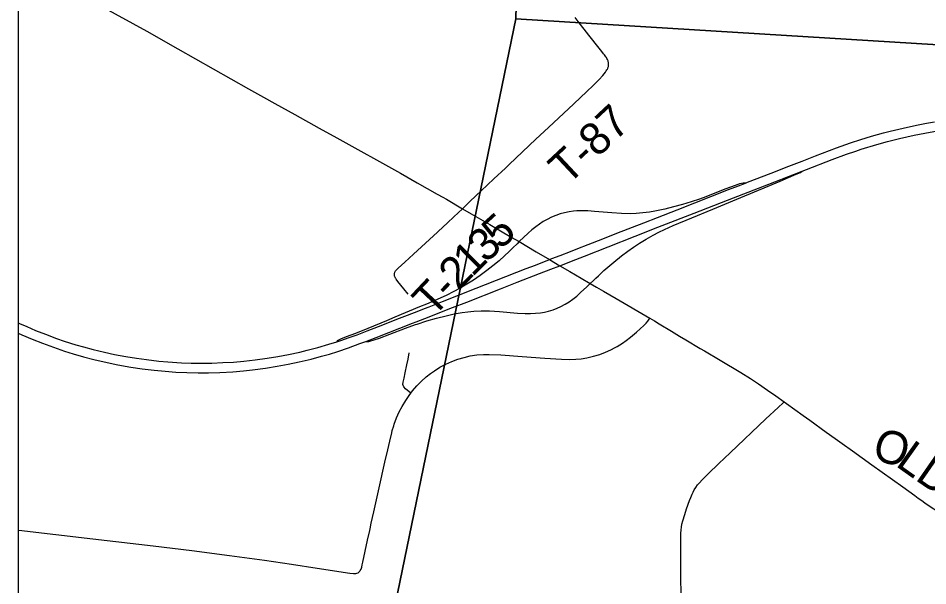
# Model space of a CAD drawing. Extents: x -13.9 to 69.1, y -25.2 to 26.1.
# Drawn here: x 1.757 to 3.245, y 17.974 to 18.903 of the extents above; entities that cross this region are included whole.
import ezdxf

# ---------------------------------------------------------------- set-up
doc = ezdxf.new("R2010")
doc.units = 0
for name, color, linetype in [('GM_X_County_Road', 7, 'Continuous'), ('GM_X_County_Road_Text', 7, 'Continuous'), ('GM_X_Interchange_Ramps', 7, 'Continuous'), ('GM_X_Township', 7, 'Continuous'), ('GM_X_Township_Road', 7, 'Continuous'), ('GM_X_Township_Road_Text', 7, 'Continuous'), ('GM_X_US_Route', 7, 'Continuous'), ('SH_Data', 7, 'Continuous')]:
    doc.layers.add(name, color=color, linetype=linetype)

msp = doc.modelspace()

# ---------------------------------------------------------------- linework, layer by layer
at = {"layer": 'GM_X_County_Road'}
for points in [[(1.8658, 18.9379), (1.8927, 18.9232), (1.9675, 18.8821), (2.0184, 18.8534), (2.1339, 18.788), (2.1583, 18.7741), (2.177, 18.7638), (2.2094, 18.7457), (2.2492, 18.7235), (2.2782, 18.7076), (2.3823, 18.6498), (2.4096, 18.6341), (2.4426, 18.6155)], [(2.4426, 18.6155), (2.4517, 18.6103), (2.4575, 18.607)], [(2.4575, 18.607), (2.4841, 18.5917)], [(2.4841, 18.5917), (2.4981, 18.5835), (2.5287, 18.5656), (2.5634, 18.5453), (2.5768, 18.5377)], [(2.5768, 18.5377), (2.6046, 18.5211), (2.6263, 18.5084), (2.6433, 18.4984), (2.6593, 18.489), (2.6782, 18.4779), (2.6928, 18.4694)], [(2.6928, 18.4694), (2.7033, 18.4633), (2.7147, 18.4566), (2.7352, 18.4447), (2.7906, 18.4124)], [(2.7906, 18.4124), (2.7979, 18.408), (2.8055, 18.4035), (2.8256, 18.3913), (2.8391, 18.3832), (2.8492, 18.3771), (2.8729, 18.3629)], [(2.8729, 18.3629), (2.8796, 18.3589), (2.9052, 18.3436), (2.9391, 18.3235), (2.9549, 18.3138), (2.9682, 18.3051), (2.9831, 18.2949), (2.9965, 18.2854), (3.0099, 18.2757)], [(2.8417, 17.9518), (2.8412, 17.9976), (2.8409, 18.047), (2.8413, 18.06), (2.8414, 18.066), (2.842, 18.0705), (2.8429, 18.0753), (2.8444, 18.0809), (2.8474, 18.0911), (2.8505, 18.1006), (2.8553, 18.1139), (2.8572, 18.119), (2.8596, 18.1244), (2.8612, 18.1278), (2.8631, 18.1314), (2.8656, 18.1353), (2.8686, 18.1396), (2.8714, 18.1432), (2.8758, 18.1477), (2.8856, 18.158), (2.903, 18.1744), (2.9218, 18.1921), (2.9803, 18.2475), (3.0002, 18.2664), (3.0083, 18.2742), (3.0099, 18.2757)], [(3.0099, 18.2757), (3.0139, 18.2728), (3.041, 18.2533), (3.0521, 18.2455), (3.0787, 18.2262), (3.0935, 18.2158), (3.1049, 18.2075), (3.1218, 18.1954), (3.1535, 18.1725), (3.2042, 18.1363), (3.2238, 18.1223), (3.2292, 18.1182), (3.2352, 18.114), (3.2403, 18.1104), (3.2524, 18.1022), (3.2595, 18.0976), (3.272, 18.09), (3.288, 18.0806), (3.3176, 18.0633), (3.3308, 18.0556)]]:
    msp.add_lwpolyline(points, dxfattribs=at)
at = {"layer": 'GM_X_Interchange_Ramps'}
for points in [[(2.6928, 18.4694), (2.6981, 18.4742), (2.7018, 18.4777), (2.7062, 18.4818), (2.7152, 18.4903), (2.7217, 18.4962), (2.7313, 18.5042), (2.7442, 18.5144), (2.7542, 18.522), (2.7639, 18.5288), (2.7733, 18.5351), (2.7843, 18.5419), (2.7956, 18.5483), (2.805, 18.5532), (2.8146, 18.5578), (2.8284, 18.564), (2.8589, 18.5765), (2.8935, 18.5908), (2.9394, 18.61), (2.984, 18.6287), (3.0034, 18.6369), (3.0258, 18.6463), (3.0353, 18.6502), (3.0367, 18.651), (3.0396, 18.6533)], [(2.9471, 18.6336), (2.9428, 18.6332), (2.9404, 18.633), (2.9373, 18.6323), (2.9341, 18.6312), (2.9299, 18.6297), (2.9147, 18.6242), (2.8995, 18.6183), (2.882, 18.6113), (2.8715, 18.6074), (2.8578, 18.6028), (2.844, 18.5987), (2.8289, 18.5946), (2.8147, 18.5909), (2.8066, 18.589), (2.7986, 18.5875), (2.7897, 18.586), (2.779, 18.5847), (2.7679, 18.5838), (2.759, 18.5834), (2.7441, 18.5839), (2.7281, 18.5849), (2.7, 18.5872), (2.6889, 18.5879), (2.6801, 18.5882), (2.6712, 18.588), (2.6657, 18.5876), (2.6586, 18.5867), (2.6505, 18.585), (2.6435, 18.583), (2.6367, 18.5806), (2.6295, 18.5776), (2.6224, 18.5741), (2.6161, 18.5705), (2.6099, 18.5665), (2.604, 18.5622), (2.5974, 18.5568), (2.5915, 18.5514), (2.5768, 18.5377)], [(2.5768, 18.5377), (2.5731, 18.5342), (2.566, 18.5276), (2.5601, 18.5214), (2.5527, 18.5143), (2.5438, 18.5063), (2.5337, 18.498), (2.5239, 18.4903), (2.5129, 18.4823), (2.5017, 18.4747), (2.4912, 18.4681), (2.48, 18.4616), (2.4686, 18.4555), (2.4581, 18.4503), (2.4424, 18.443), (2.4249, 18.4356), (2.4137, 18.4309), (2.3734, 18.4142), (2.3594, 18.4084), (2.329, 18.3957), (2.3088, 18.3875), (2.2937, 18.3817), (2.2845, 18.3783), (2.282, 18.3771), (2.2801, 18.3761), (2.279, 18.3752), (2.2782, 18.3739)], [(2.3259, 18.3745), (2.3286, 18.3741), (2.3305, 18.3743), (2.3324, 18.3747), (2.3483, 18.38), (2.365, 18.3862), (2.3906, 18.3959), (2.4073, 18.4019), (2.41, 18.4029), (2.4253, 18.4079), (2.4414, 18.4125), (2.457, 18.4164), (2.4705, 18.4194), (2.4831, 18.4216), (2.4924, 18.4229), (2.5023, 18.4239), (2.5145, 18.4245), (2.5283, 18.4244), (2.5443, 18.4234), (2.5741, 18.4209), (2.5863, 18.4202), (2.5951, 18.4202), (2.6034, 18.4205), (2.6117, 18.4214), (2.6182, 18.4225), (2.6247, 18.424), (2.6322, 18.4262), (2.6389, 18.4288), (2.645, 18.4316), (2.6519, 18.4354), (2.6582, 18.4392), (2.6642, 18.4434), (2.6709, 18.4487), (2.6772, 18.4545), (2.6872, 18.4639), (2.6928, 18.4694)]]:
    msp.add_lwpolyline(points, dxfattribs=at)
at = {"layer": 'GM_X_Township'}
msp.add_lwpolyline([(8.0976, 21.2145), (2.668, 21.2145), (2.5713, 21.1249), (2.5376, 21.0933), (2.5207, 21.0774), (2.9282, 20.5283), (2.3149, 19.9943), (2.3345, 19.9924), (2.4186, 19.989), (2.4692, 19.987), (2.5176, 19.987), (2.5995, 20.0118), (2.5714, 18.9023), (4.5288, 18.7816), (7.8661, 18.459), (7.9988, 20.0382), (8.0428, 20.5625)], close=True, dxfattribs=at)
for points in [[(2.2023, 16.145), (2.216, 16.457), (2.1711, 16.462), (2.1794, 16.5325), (2.2304, 17.2467), (2.5714, 18.9023), (2.5995, 20.0118)], [(1.7571, 19.5083), (1.7571, 15.7823)], [(7.8661, 18.459), (4.5288, 18.7816), (2.5714, 18.9023), (2.2304, 17.2467), (2.1794, 16.5325), (2.1711, 16.462), (2.216, 16.457), (2.2023, 16.145)]]:
    msp.add_lwpolyline(points, dxfattribs=at)
at = {"layer": 'GM_X_Township_Road'}
for points in [[(2.5542, 18.6582), (2.5604, 18.6639), (2.604, 18.7052), (2.6244, 18.7244), (2.6662, 18.7633), (2.6875, 18.7832), (2.6978, 18.7932), (2.7073, 18.8031), (2.7136, 18.8099), (2.718, 18.8153), (2.7192, 18.8172), (2.7201, 18.8188), (2.7209, 18.8201), (2.7214, 18.8213), (2.7218, 18.8222), (2.7222, 18.8234), (2.7225, 18.8245), (2.7227, 18.826), (2.7228, 18.8271), (2.7228, 18.8283), (2.7227, 18.8295), (2.7226, 18.8309), (2.7224, 18.8322), (2.7221, 18.8334), (2.7217, 18.8344), (2.7212, 18.8356), (2.7202, 18.8376), (2.7193, 18.839), (2.7185, 18.8403), (2.7174, 18.8417), (2.7161, 18.8435), (2.7147, 18.8452), (2.7118, 18.8488), (2.7074, 18.8542), (2.6905, 18.8755), (2.6733, 18.898), (2.6683, 18.9045)], [(2.4841, 18.5917), (2.4898, 18.5972), (2.4967, 18.604), (2.5146, 18.6209), (2.5354, 18.6405), (2.5542, 18.6582)], [(2.4429, 18.5533), (2.4442, 18.5545), (2.4593, 18.5684), (2.4697, 18.5782), (2.4841, 18.5917)], [(2.3949, 18.4518), (2.3879, 18.4603), (2.3781, 18.4725), (2.3754, 18.4763), (2.3748, 18.4773), (2.3743, 18.4781), (2.3736, 18.4795), (2.3732, 18.4804), (2.3729, 18.4814), (2.3728, 18.4822), (2.3727, 18.4833), (2.3726, 18.4843), (2.3727, 18.4852), (2.3729, 18.4863), (2.3731, 18.4872), (2.3734, 18.488), (2.3739, 18.4889), (2.3743, 18.4897), (2.3751, 18.4906), (2.3758, 18.4915), (2.3769, 18.4927), (2.3786, 18.4943), (2.3896, 18.5043), (2.4039, 18.5173), (2.4429, 18.5533)], [(2.7335, 18.3643), (2.7367, 18.366), (2.7457, 18.3716), (2.7517, 18.3758), (2.7588, 18.3813), (2.7688, 18.3898), (2.7806, 18.4006), (2.7842, 18.4042), (2.7871, 18.4076), (2.7906, 18.4124)], [(2.3993, 18.2899), (2.4021, 18.2936), (2.409, 18.3015), (2.4166, 18.3093), (2.4247, 18.3166), (2.4314, 18.3219), (2.4379, 18.3265), (2.4471, 18.3322), (2.4565, 18.3373), (2.4662, 18.3418), (2.4762, 18.3454), (2.4864, 18.3484), (2.4962, 18.3506), (2.5072, 18.3523), (2.5183, 18.3531), (2.5277, 18.353), (2.5465, 18.3524), (2.5813, 18.35), (2.6188, 18.3471), (2.6458, 18.3454), (2.6596, 18.3451), (2.6695, 18.3454), (2.6783, 18.3462), (2.6875, 18.3477), (2.6983, 18.3501), (2.7088, 18.3533), (2.7177, 18.3566), (2.7263, 18.3605), (2.7335, 18.3643)], [(2.3865, 18.3039), (2.3869, 18.3076), (2.3879, 18.3122), (2.3883, 18.3141), (2.3903, 18.3233), (2.3931, 18.3362), (2.395, 18.3453), (2.3969, 18.3557)], [(2.3993, 18.2899), (2.3908, 18.2968), (2.388, 18.3003), (2.3865, 18.3039)], [(2.3714, 18.2361), (2.3724, 18.2393), (2.3761, 18.2493), (2.3804, 18.259), (2.385, 18.2679), (2.391, 18.278), (2.3965, 18.2862), (2.3993, 18.2899)], [(2.3683, 18.2251), (2.3691, 18.2285), (2.3714, 18.2361)], [(2.3616, 18.1973), (2.3648, 18.2112), (2.3683, 18.2251)], [(2.3347, 18.0771), (2.3386, 18.0956), (2.3476, 18.1349), (2.3571, 18.1771), (2.3616, 18.1973)], [(1.7571, 18.0654), (1.7581, 18.0653), (1.879, 18.0512), (1.978, 18.0397), (2.0412, 18.0322), (2.1026, 18.0243), (2.1602, 18.0165), (2.2041, 18.0101), (2.2462, 18.0036), (2.2998, 17.9953), (2.3058, 17.9947), (2.3095, 17.9949), (2.3112, 17.9953), (2.313, 17.996), (2.3143, 17.9971), (2.3157, 17.9983), (2.3166, 17.9994)], [(2.3166, 17.9994), (2.318, 18.002), (2.3191, 18.0051), (2.32, 18.0086), (2.3211, 18.0133), (2.3286, 18.0493), (2.3321, 18.065)], [(2.3321, 18.065), (2.3327, 18.0678), (2.3347, 18.0771)]]:
    msp.add_lwpolyline(points, dxfattribs=at)
at = {"layer": 'GM_X_US_Route'}
for points in [[(1.7571, 18.4048), (1.7592, 18.4038), (1.771, 18.3986), (1.7855, 18.3925), (1.8016, 18.3862), (1.8199, 18.3795), (1.8325, 18.3751), (1.8516, 18.369), (1.8639, 18.3655), (1.8795, 18.3613), (1.8984, 18.3569), (1.9147, 18.3533), (1.9332, 18.3498), (1.9507, 18.3469), (1.9672, 18.3446), (1.987, 18.3423), (2.0019, 18.3409), (2.0245, 18.3395), (2.04, 18.339), (2.0561, 18.3388), (2.0738, 18.339), (2.092, 18.3397), (2.1092, 18.3407), (2.1263, 18.3422), (2.145, 18.3442), (2.1642, 18.3469), (2.1817, 18.3498), (2.1991, 18.353), (2.2176, 18.357), (2.23, 18.36), (2.2472, 18.3646), (2.2654, 18.3698), (2.2782, 18.3739), (2.285, 18.376), (2.2987, 18.3807), (2.3118, 18.3854), (2.328, 18.3916), (2.3467, 18.399), (2.381, 18.4124), (2.394, 18.4174), (2.4123, 18.4246), (2.4215, 18.4282), (2.4293, 18.4313), (2.4511, 18.4399), (2.5062, 18.4614), (2.5882, 18.4936), (2.6033, 18.4994), (2.6263, 18.5084), (2.6303, 18.51), (2.6439, 18.5152), (2.6605, 18.5216), (2.6724, 18.5264), (2.6896, 18.533), (2.7135, 18.5422), (2.7363, 18.5514), (2.7805, 18.5687), (2.8028, 18.5773), (2.8351, 18.5898), (2.9192, 18.6228), (2.9354, 18.629), (2.9471, 18.6336), (2.9504, 18.6349), (2.9889, 18.6498), (3.018, 18.6612), (3.0393, 18.6697), (3.0616, 18.6784), (3.0955, 18.6912), (3.1186, 18.6994), (3.1355, 18.7049), (3.153, 18.7102), (3.1728, 18.7157), (3.1836, 18.7184), (3.2046, 18.7234), (3.2268, 18.7282), (3.2431, 18.7314), (3.2562, 18.7337)], [(2.6584, 18.5043), (2.6623, 18.5058), (2.6836, 18.5141), (2.722, 18.5292), (2.7661, 18.5467), (2.8035, 18.5612), (2.8249, 18.5695), (2.8488, 18.5788), (2.8628, 18.5843), (2.9173, 18.6057), (2.9948, 18.6358), (3.0396, 18.6533), (3.0467, 18.656), (3.0889, 18.6722), (3.1119, 18.6807), (3.1272, 18.686), (3.1362, 18.689), (3.1618, 18.6968), (3.1794, 18.7017), (3.1988, 18.7066), (3.2227, 18.7119), (3.2401, 18.7155), (3.2608, 18.7192)], [(1.7571, 18.3877), (1.7632, 18.385), (1.7797, 18.3781), (1.7968, 18.3714), (1.8146, 18.3649), (1.833, 18.3586), (1.8473, 18.3541), (1.8638, 18.3493), (1.881, 18.3447), (1.9026, 18.3397), (1.9199, 18.3361), (1.9412, 18.3324), (1.9598, 18.3297), (1.9795, 18.3273), (1.9977, 18.3256), (2.0148, 18.3243), (2.033, 18.3234), (2.0517, 18.323), (2.0683, 18.3231), (2.0871, 18.3237), (2.108, 18.3248), (2.1256, 18.3263), (2.1405, 18.3279), (2.1619, 18.3308), (2.181, 18.3338), (2.1989, 18.3371), (2.2168, 18.3409), (2.2362, 18.3455), (2.2534, 18.3501), (2.2662, 18.3538), (2.2799, 18.3582), (2.2973, 18.364), (2.3162, 18.3708), (2.3259, 18.3745), (2.3428, 18.3809), (2.4019, 18.4042), (2.4083, 18.4067), (2.4222, 18.4122), (2.4674, 18.4297), (2.4908, 18.4389), (2.5459, 18.4605), (2.5734, 18.4713), (2.6098, 18.4854), (2.6285, 18.4927), (2.6433, 18.4984), (2.6584, 18.5043)]]:
    msp.add_lwpolyline(points, dxfattribs=at)
at = {"layer": 'SH_Data'}
msp.add_line((1.7571, 21.2145), (1.7571, 14.4145), dxfattribs=at)

# ---------------------------------------------------------------- texts
at = {"layer": 'GM_X_County_Road_Text'}
for s, height, rotation, p in [('O', 0.0541, 342.755, (3.1516, 18.1832)), ('L', 0.0532, 324.5554, (3.1906, 18.1718)), ('D', 0.0533, 325.2561, (3.2227, 18.1489))]:
    msp.add_text(s, height=height, rotation=rotation, dxfattribs=at).set_placement(p)
at = {"layer": 'GM_X_Township_Road_Text'}
for s, height, rotation, p in [('T-87', 0.05276, 43.0679, (2.6558, 18.6287)), ('5', 0.0528, 42.4934, (2.5458, 18.5233)), ('3', 0.0528, 43.07, (2.5224, 18.5014)), ('1', 0.0527, 44.4567, (2.4997, 18.4791)), ('2', 0.0526, 45.4684, (2.4772, 18.4562)), ('T', 0.0525, 46.7494, (2.4357, 18.4123)), ('-', 0.0525, 46.3779, (2.4625, 18.4408))]:
    msp.add_text(s, height=height, rotation=rotation, dxfattribs=at).set_placement(p)

doc.saveas('drawing.dxf')
